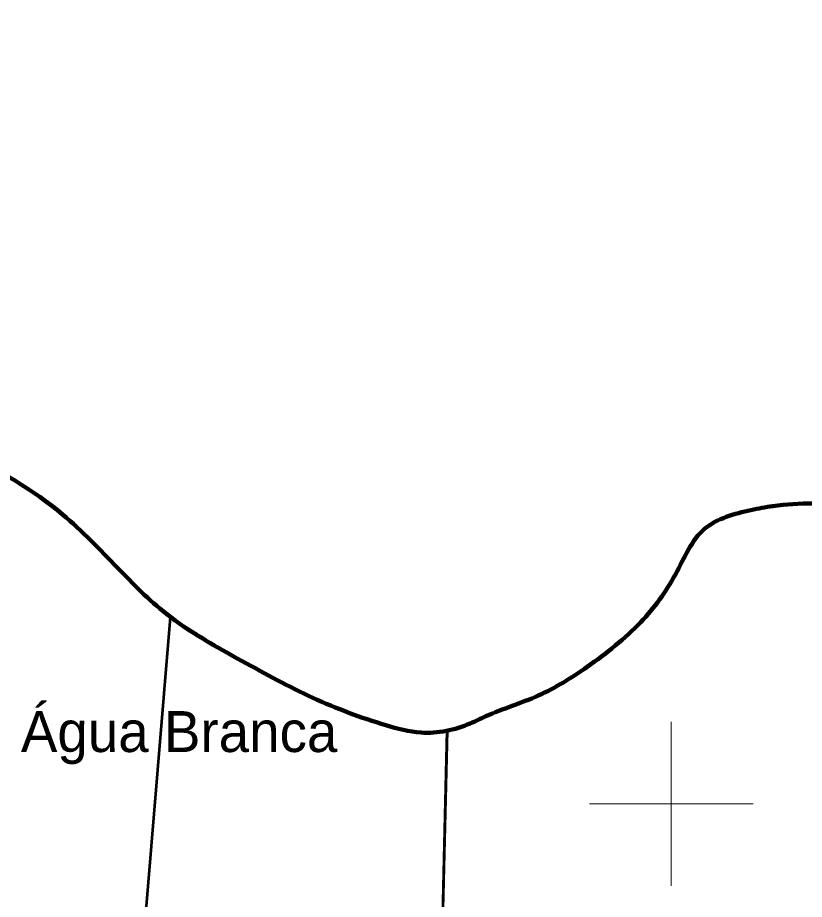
# Model space of a CAD drawing. Extents: x -1643653 to 4543381, y 1624270 to 13878484.
# Drawn here: x 617017 to 626625, y 8973834 to 8984602 of the extents above; entities that cross this region are included whole.
import ezdxf

# ---------------------------------------------------------------- set-up
doc = ezdxf.new("R2010")
doc.units = 0
doc.header["$LTSCALE"] = 200
for name, color, linetype, lineweight in [('1', 7, 'Continuous', 13), ('2', 7, 'Continuous', 13), ('26', 7, 'Continuous', 106), ('27', 7, 'Continuous', 53), ('28', 7, 'Continuous', 53)]:
    doc.layers.add(name, color=color, linetype=linetype, lineweight=lineweight)
doc.layers.add('41', color=7, linetype='Continuous')

msp = doc.modelspace()

# ---------------------------------------------------------------- linework, layer by layer
at = {"layer": '1', "lineweight": 25}
msp.add_spline([(814781, 9009175.5), (814787.2, 9009173.4), (814796.9, 9009173.4), (814799.4, 9009172.4), (814805.1, 9009174.5), (814805.6, 9009176.5), (814811.7, 9009179.5), (814811.7, 9009179.5), (814801.5, 9009181), (814790.7, 9009181.5), (814784.1, 9009183.1), (814777.4, 9009185.1), (814778.4, 9009175.5)], degree=3, dxfattribs=at)
at = {"layer": '2'}
for p, q in [((625000, 8974000), (625000, 8976000)), ((624000, 8975000), (626000, 8975000))]:
    msp.add_line(p, q, dxfattribs=at)
at = {"layer": '26'}
msp.add_spline([(593042.9, 8976356.4), (593459.4, 8976419.7), (594161.8, 8976760.1), (594545.8, 8977114.6), (594814.3, 8977291.5), (596052.8, 8977846), (596780.5, 8978160.9), (597647.4, 8978322.7), (598691.5, 8978280.2), (599825, 8978301), (600207.2, 8978324.8), (600219.9, 8978324.8), (601225.9, 8978295.2), (602040.5, 8978228.3), (602729, 8978352.6), (603275.7, 8978615.7), (603826.1, 8978691.5), (605382.2, 8979104.7), (606925.6, 8979530.7), (607614.7, 8979782.2), (608494.2, 8979905.8), (609628.7, 8980104.6), (610966.5, 8980200.8), (612239.3, 8980081.1), (613131.4, 8980179.2), (614149.6, 8980073.3), (614581.8, 8979931.6), (616361, 8979275.7), (617566.6, 8978533.2), (618237.8, 8977881.9), (618833.2, 8977319.9), (619759.6, 8976743.8), (620623, 8976295.2), (621512.5, 8975960.9), (621945, 8975870.1), (622544.2, 8975982.1), (622735.8, 8976070.3), (623374, 8976322), (623974.5, 8976675.6), (624627.1, 8977219.8), (625050.7, 8977803), (625410.5, 8978361.1), (625972.2, 8978587.6), (626239.9, 8978637.4), (628239.2, 8978616.5), (629272.1, 8978853.8), (630051.8, 8979346.6), (630703.5, 8979738.1), (631164.1, 8980105), (631534.8, 8980357.8), (632185.7, 8980596.8), (632989, 8980758.8), (633690, 8980870.4), (634328.2, 8981109.3), (634980.1, 8981526.3), (636460.7, 8982117.9), (637495.4, 8982660.5), (638159.4, 8982975.7), (638593.8, 8983228.2), (639449.6, 8983669.8), (641371.6, 8983483.9), (642032.9, 8983315.8), (642528.8, 8983186.6), (643277.3, 8982687.6), (644168, 8982544), (644675.9, 8982274.9), (645321.7, 8981636.4), (645853, 8981011.1), (646805.1, 8980473.1), (647606.1, 8980240.8), (648482.7, 8979868.5), (649626.6, 8979469.5), (650871.6, 8978943), (651404, 8978495.7), (652521.8, 8977995.2), (653308.2, 8977445.1), (653712.6, 8976883.9), (654308.9, 8976487.2), (655070.4, 8976039), (655983.7, 8975399.4)], degree=3, dxfattribs=at)
at = {"layer": '27'}
for p, q in [((618878.3, 8977281.1), (617915.3, 8965604.9)), ((618878.3, 8977281.1), (617915.3, 8965604.9)), ((622261.6, 8975895.3), (622031.1, 8965989.3))]:
    msp.add_line(p, q, dxfattribs=at)
msp.add_lwpolyline([(621430.6, 8965386.2), (622031.1, 8965989.3), (622261.6, 8975895.3)], dxfattribs=at)
for points in [[(613948.8, 8980121), (614149.6, 8980073.3), (614581.8, 8979931.6), (616361, 8979275.7), (617566.6, 8978533.2), (618237.8, 8977881.9), (618833.2, 8977319.9), (618878.3, 8977281.1)], [(628372, 8978627.3), (628239.2, 8978616.5), (626239.9, 8978637.4), (625972.2, 8978587.6), (625410.5, 8978361.1), (625050.7, 8977803), (624627.1, 8977219.8), (623974.5, 8976675.6), (623374, 8976322), (622735.8, 8976070.3), (622544.2, 8975982.1), (622261.6, 8975895.3)], [(622261.6, 8975895.3), (621945, 8975870.1), (621512.5, 8975960.9), (620623, 8976295.2), (619759.6, 8976743.8), (618878.3, 8977281.1)]]:
    msp.add_spline(points, degree=3, dxfattribs=at)
at = {"layer": '28'}
msp.add_spline([(628372, 8978627.3), (628239.2, 8978616.5), (626239.9, 8978637.4), (625972.2, 8978587.6), (625410.5, 8978361.1), (625050.7, 8977803), (624627.1, 8977219.8), (623974.5, 8976675.6), (623374, 8976322), (622735.8, 8976070.3), (622544.2, 8975982.1), (621945, 8975870.1), (621512.5, 8975960.9), (620623, 8976295.2), (619759.6, 8976743.8), (618833.2, 8977319.9), (618237.8, 8977881.9), (617566.6, 8978533.2), (616361, 8979275.7), (614581.8, 8979931.6), (614149.6, 8980073.3), (613948.8, 8980121)], degree=3, dxfattribs=at)
msp.add_spline([(628372, 8978627.3), (628239.2, 8978616.5), (626239.9, 8978637.4), (625972.2, 8978587.6), (625410.5, 8978361.1), (625050.7, 8977803), (624627.1, 8977219.8), (623974.5, 8976675.6), (623374, 8976322), (622735.8, 8976070.3), (622544.2, 8975982.1), (621945, 8975870.1), (621512.5, 8975960.9), (620623, 8976295.2), (619759.6, 8976743.8), (618833.2, 8977319.9), (618237.8, 8977881.9), (617566.6, 8978533.2), (616361, 8979275.7), (614581.8, 8979931.6), (614149.6, 8980073.3), (613948.8, 8980121)], degree=3, dxfattribs=at)

# ---------------------------------------------------------------- texts
at = {"layer": '41'}
msp.add_text('Água Branca', height=500, dxfattribs=at).set_placement((617056.5, 8975633.4))

doc.saveas('drawing.dxf')
